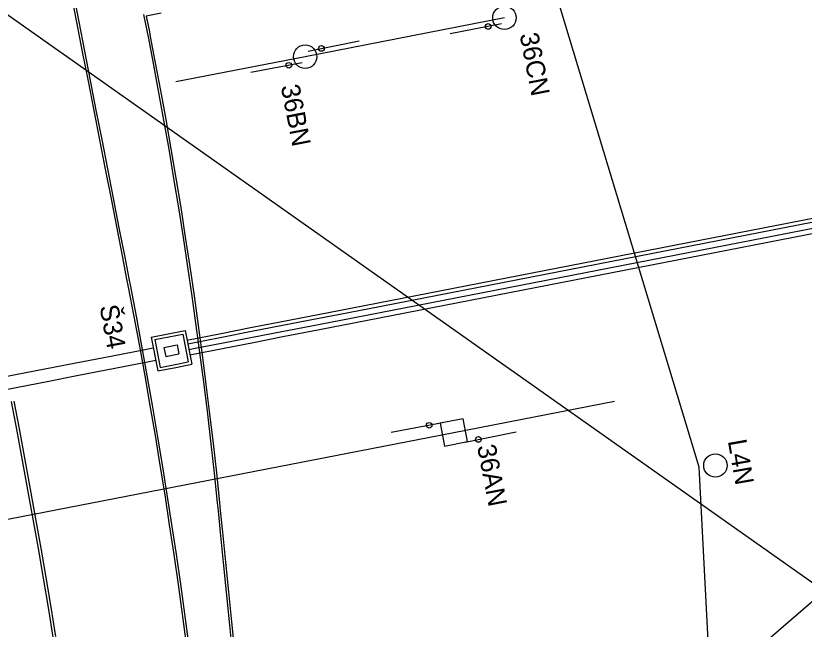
# Model space of a CAD drawing. Extents: x -545258 to -544992, y -1122311 to -1121664.
# Drawn here: x -545154.3 to -545101.7, y -1121989.4 to -1121948.4 of the extents above; entities that cross this region are included whole.
import ezdxf

# ---------------------------------------------------------------- set-up
doc = ezdxf.new("R2010")
doc.units = 0
for name, color, linetype in [('SO 18-01-01_3', 7, 'Continuous'), ('SO 18-01-01_4', 7, 'Continuous'), ('SO18-15-08_def', 7, 'Continuous'), ('SO18-16-02', 7, 'Continuous'), ('SO18-16-03', 7, 'Continuous'), ('SOPS', 7, 'Continuous')]:
    doc.layers.add(name, color=color, linetype=linetype)

msp = doc.modelspace()

# ---------------------------------------------------------------- linework, layer by layer
at = {"layer": 'SO 18-01-01_3'}
for p, q in [((-545121.686, -1121948.581), (-545134.976, -1121951.171)), ((-545121.889, -1121948.981), (-545125.3, -1121949.646)), ((-545134.772, -1121950.795), (-545131.363, -1121950.122)), ((-545134.976, -1121951.171), (-545143.602, -1121952.853)), ((-545135.18, -1121951.572), (-545138.59, -1121952.237)), ((-545125.064, -1121976.248), (-545114.335, -1121974.156)), ((-545125.825, -1121975.601), (-545129.236, -1121976.266)), ((-545155.976, -1121982.273), (-545125.064, -1121976.248)), ((-545124.302, -1121976.892), (-545120.893, -1121976.219))]:
    msp.add_line(p, q, dxfattribs=at)
msp.add_lwpolyline([(-545125.979, -1121975.631), (-545125.68, -1121977.162), (-545124.149, -1121976.864), (-545124.448, -1121975.333)], close=True, dxfattribs=at)
for centre, radius in [((-545121.686, -1121948.58), 0.78), ((-545122.771, -1121949.153), 0.187), ((-545134.976, -1121951.171), 0.78), ((-545133.891, -1121950.621), 0.187), ((-545136.061, -1121951.744), 0.187), ((-545126.707, -1121975.773), 0.187), ((-545123.421, -1121976.718), 0.187), ((-545107.617, -1121978.456), 0.78)]:
    msp.add_circle(centre, radius, dxfattribs=at)
at = {"layer": 'SO 18-01-01_4'}
msp.add_lwpolyline([(-545102.793, -1122250.491), (-545106.116, -1122208.618), (-545109.928, -1122137.596), (-545106.412, -1122088.188), (-545106.367, -1122023.596), (-545108.703, -1121978.559), (-545127.424, -1121916.593), (-545139.015, -1121857.213), (-545147.82, -1121812.064), (-545159.299, -1121753.172), (-545170.035, -1121688.35), (-545174.127, -1121676.058)], dxfattribs=at)
msp.add_circle((-545107.617, -1121978.456), 0.78, dxfattribs=at)
at = {"layer": 'SO18-15-08_def'}
for p, q in [((-545142.983, -1121969.447), (-545142.543, -1121971.705)), ((-545145.241, -1121969.887), (-545144.801, -1121972.145)), ((-545145.006, -1121970.045), (-545144.643, -1121971.91)), ((-545143.142, -1121969.682), (-545142.778, -1121971.546)), ((-545144.391, -1121970.587), (-545144.277, -1121971.176)), ((-545143.508, -1121970.415), (-545143.393, -1121971.004))]:
    msp.add_line(p, q, dxfattribs=at)
for points in [[(-545142.859, -1121970.085), (-545140.574, -1121969.64), (-545138.611, -1121969.257), (-545136.648, -1121968.874), (-545134.685, -1121968.492), (-545132.722, -1121968.109), (-545096.666, -1121961.082)], [(-545142.811, -1121970.33), (-545140.526, -1121969.885), (-545138.563, -1121969.502), (-545136.6, -1121969.12), (-545134.637, -1121968.737), (-545132.674, -1121968.354), (-545130.711, -1121967.972), (-545096.618, -1121961.325)], [(-545142.735, -1121970.723), (-545142.413, -1121970.66), (-545140.45, -1121970.278), (-545138.487, -1121969.895), (-545136.524, -1121969.512), (-545134.561, -1121969.13), (-545132.598, -1121968.747), (-545096.541, -1121961.72)], [(-545142.668, -1121971.067), (-545140.383, -1121970.621), (-545138.42, -1121970.238), (-545136.457, -1121969.856), (-545134.494, -1121969.473), (-545132.531, -1121969.09), (-545096.474, -1121962.063)], [(-545145.241, -1121969.887), (-545142.983, -1121969.447)], [(-545145.006, -1121970.045), (-545143.142, -1121969.682)], [(-545144.391, -1121970.587), (-545143.508, -1121970.415)], [(-545156.576, -1121972.835), (-545156.264, -1121972.774), (-545154.301, -1121972.392), (-545152.338, -1121972.009), (-545150.375, -1121971.626), (-545148.412, -1121971.244), (-545146.449, -1121970.861), (-545145.102, -1121970.599)], [(-545144.277, -1121971.176), (-545143.393, -1121971.004)], [(-545156.414, -1121973.67), (-545156.102, -1121973.609), (-545154.138, -1121973.226), (-545152.175, -1121972.843), (-545150.212, -1121972.461), (-545148.249, -1121972.078), (-545146.286, -1121971.695), (-545144.94, -1121971.433)], [(-545144.643, -1121971.91), (-545143.645, -1121971.715), (-545142.778, -1121971.546)], [(-545144.801, -1121972.145), (-545143.606, -1121971.912), (-545142.543, -1121971.705)]]:
    msp.add_lwpolyline(points, dxfattribs=at)
at = {"layer": 'SO18-16-02'}
for points in [[(-545154.572, -1121974.197), (-545154.203, -1121976.156), (-545153.84, -1121978.117), (-545153.484, -1121980.079), (-545153.135, -1121982.042), (-545152.792, -1121984.006), (-545152.455, -1121985.971), (-545152.125, -1121987.937), (-545151.802, -1121989.905)], [(-545154.395, -1121974.163), (-545154.026, -1121976.123), (-545153.663, -1121978.085), (-545153.307, -1121980.047), (-545152.957, -1121982.01), (-545152.614, -1121983.975), (-545152.278, -1121985.941), (-545151.947, -1121987.908), (-545151.624, -1121989.876)]]:
    msp.add_lwpolyline(points, dxfattribs=at)
at = {"layer": 'SO18-16-03'}
msp.add_line((-545144.58, -1121948.272), (-545145.57, -1121948.469), dxfattribs=at)
for points in [[(-545150.603, -1121946.911), (-545150.22, -1121948.875), (-545149.838, -1121950.838), (-545149.455, -1121952.801), (-545149.072, -1121954.764), (-545148.69, -1121956.727), (-545148.307, -1121958.69), (-545147.924, -1121960.653), (-545147.542, -1121962.616), (-545147.159, -1121964.579), (-545146.88, -1121966.011), (-545146.776, -1121966.548), (-545146.399, -1121968.522), (-545146.031, -1121970.501), (-545145.673, -1121972.481), (-545145.326, -1121974.464), (-545144.988, -1121976.447), (-545144.66, -1121978.433), (-545144.342, -1121980.42), (-545144.034, -1121982.409), (-545143.736, -1121984.399), (-545143.448, -1121986.391), (-545143.17, -1121988.384), (-545142.901, -1121990.379)], [(-545150.456, -1121946.883), (-545150.073, -1121948.846), (-545149.69, -1121950.809), (-545149.308, -1121952.772), (-545148.925, -1121954.735), (-545148.542, -1121956.698), (-545148.16, -1121958.661), (-545147.777, -1121960.624), (-545147.394, -1121962.587), (-545147.012, -1121964.55), (-545146.733, -1121965.982), (-545146.628, -1121966.519), (-545146.251, -1121968.494), (-545145.884, -1121970.474), (-545145.526, -1121972.455), (-545145.178, -1121974.438), (-545144.84, -1121976.423), (-545144.512, -1121978.409), (-545144.194, -1121980.397), (-545143.886, -1121982.387), (-545143.588, -1121984.378), (-545143.299, -1121986.37), (-545143.021, -1121988.364), (-545142.753, -1121990.359)], [(-545145.746, -1121948.351), (-545145.513, -1121949.544), (-545145.453, -1121949.852), (-545145.137, -1121951.495), (-545144.772, -1121953.446), (-545144.418, -1121955.399), (-545144.076, -1121957.355), (-545143.745, -1121959.312), (-545143.425, -1121961.271), (-545143.116, -1121963.231), (-545142.818, -1121965.194), (-545142.531, -1121967.158), (-545142.256, -1121969.123), (-545141.992, -1121971.09), (-545141.739, -1121973.059), (-545141.498, -1121975.029), (-545141.267, -1121977.001), (-545141.048, -1121978.973), (-545140.84, -1121980.95), (-545140.787, -1121981.474), (-545140.64, -1121982.933), (-545140.44, -1121984.923), (-545140.239, -1121986.913), (-545140.038, -1121988.903), (-545139.838, -1121990.893)], [(-545145.57, -1121948.469), (-545145.366, -1121949.516), (-545145.306, -1121949.824), (-545144.99, -1121951.467), (-545144.625, -1121953.419), (-545144.271, -1121955.373), (-545143.928, -1121957.329), (-545143.597, -1121959.287), (-545143.276, -1121961.247), (-545142.967, -1121963.208), (-545142.669, -1121965.171), (-545142.383, -1121967.136), (-545142.107, -1121969.103), (-545141.843, -1121971.071), (-545141.59, -1121973.041), (-545141.349, -1121975.012), (-545141.118, -1121976.984), (-545140.899, -1121978.957), (-545140.691, -1121980.935), (-545140.638, -1121981.459), (-545140.491, -1121982.918), (-545140.29, -1121984.908), (-545140.09, -1121986.898), (-545139.889, -1121988.888), (-545139.688, -1121990.878)]]:
    msp.add_lwpolyline(points, dxfattribs=at)
at = {"layer": 'SOPS'}
for q in [(-545195.929, -1121919.376), (-545175.795, -1122052.141)]:
    msp.add_line((-545100.371, -1121986.851), q, dxfattribs=at)

# ---------------------------------------------------------------- texts
at = {"layer": 'SO 18-01-01_3'}
for s, p in [('36CN', (-545120.678, -1121949.688)), ('36BN', (-545136.604, -1121953.142)), ('36AN', (-545123.516, -1121977.173))]:
    msp.add_text(s, height=1.25, rotation=280.9571, dxfattribs=at).set_placement(p)
at = {"layer": 'SO 18-01-01_4'}
msp.add_text('L4N', height=1.25, rotation=280.0029, dxfattribs=at).set_placement((-545106.792, -1121976.817))
at = {"layer": 'SO18-15-08_def'}
msp.add_text('Š34', height=1.25, rotation=280.4462, dxfattribs=at).set_placement((-545148.692, -1121967.839))

doc.saveas('drawing.dxf')
